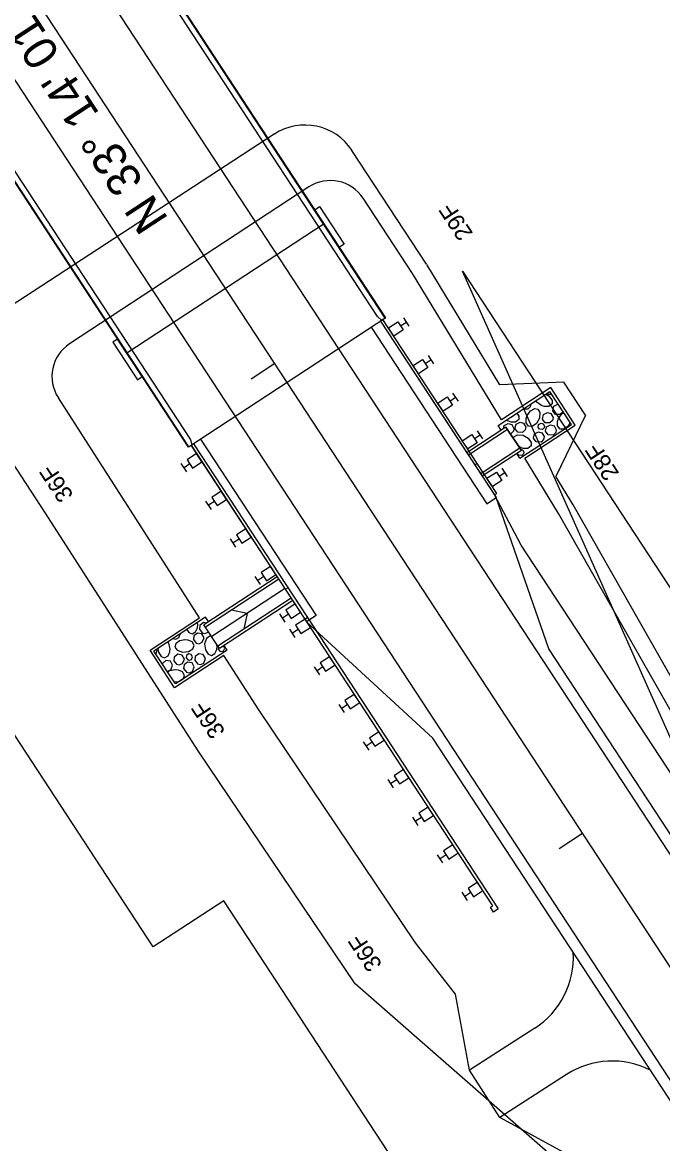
# Model space of a CAD drawing. Extents: x 1551641 to 1624343, y 1119533 to 1136600.
# Drawn here: x 1552624.3 to 1552738.3, y 1134110 to 1134309.5 of the extents above; entities that cross this region are included whole.
import ezdxf

# ---------------------------------------------------------------- set-up
doc = ezdxf.new("R2010")
doc.units = 0
for name, color, linetype in [('BR_CONCRETE', 7, 'Continuous'), ('Drainage-Trench', 7, 'Continuous'), ('RD_HC_CL_Rel', 7, 'Continuous'), ('RD_HC_Data', 7, 'Continuous'), ('RD_HC_Data_Tic', 7, 'Continuous'), ('RD_PD_BOC', 7, 'Continuous'), ('RD_PD_CstnLmt', 7, 'Continuous'), ('RD_PD_CstnLmt_TX', 7, 'Continuous'), ('RD_PD_DR_ErosCtrl', 7, 'Continuous'), ('RD_PD_DR_Inlet', 7, 'Continuous'), ('RD_PD_Driveway', 7, 'Continuous'), ('RD_PD_Final_TrvlWay', 7, 'Continuous'), ('RD_PD_GR', 7, 'Continuous'), ('RD_PD_PatLn1', 7, 'Continuous'), ('RD_PD_PaveDit', 7, 'Continuous'), ('RD_PD_PaveShd', 7, 'Continuous'), ('RD_PD_RW', 7, 'Continuous'), ('RD_Sketch8', 7, 'Continuous')]:
    doc.layers.add(name, color=color, linetype=linetype)

# ---------------------------------------------------------------- blocks, each defined once
blk = doc.blocks.new('Guardrail_MTBBC3_Transition')
at = {"layer": 'RD_PD_GR'}
for p, q in [((3.525, 3.75), (1.775, 3.75)), ((1.775, 0.5), (1.775, 2.5)), ((1.775, 2.5), (3.525, 2.5)), ((2.65, 2.5), (2.65, 3.75)), ((3.525, 2.5), (3.525, 0.5)), ((11.525, 3.75), (9.775, 3.75)), ((9.775, 0.5), (9.775, 2.5)), ((9.775, 2.5), (11.525, 2.5)), ((10.65, 2.5), (10.65, 3.75)), ((11.525, 2.5), (11.525, 0.5)), ((19.525, 3.75), (17.775, 3.75)), ((17.775, 0.5), (17.775, 2.5)), ((17.775, 2.5), (19.525, 2.5)), ((18.65, 2.5), (18.65, 3.75)), ((19.525, 2.5), (19.525, 0.5)), ((27.525, 3.75), (25.775, 3.75)), ((25.775, 0.5), (25.775, 2.5)), ((25.775, 2.5), (27.525, 2.5)), ((26.65, 2.5), (26.65, 3.75)), ((27.525, 2.5), (27.525, 0.5)), ((35.525, 3.75), (33.775, 3.75)), ((33.775, 0.5), (33.775, 2.5)), ((33.775, 2.5), (35.525, 2.5)), ((34.65, 2.5), (34.65, 3.75)), ((35.525, 2.5), (35.525, 0.5)), ((37, 0.5), (0, 0.5)), ((0, 0.5), (0, 0)), ((0, 0), (37, 0)), ((3.525, 0.5), (1.775, 0.5)), ((11.525, 0.5), (9.775, 0.5)), ((19.525, 0.5), (17.775, 0.5)), ((27.525, 0.5), (25.775, 0.5)), ((30.65, 0.5), (30.65, 0)), ((35.525, 0.5), (33.775, 0.5)), ((37, 0), (37, 0.5))]:
    blk.add_line(p, q, dxfattribs=at)

msp = doc.modelspace()

# ---------------------------------------------------------------- linework, layer by layer
at = {"layer": 'BR_CONCRETE'}
for p, q in [((1552688.91, 1134256.91), (1552612.18, 1134374.01)), ((1552688.98, 1134256.95), (1552612.25, 1134374.05)), ((1552653.85, 1134233.93), (1552577.12, 1134351.04)), ((1552653.92, 1134233.98), (1552577.19, 1134351.08)), ((1552678.02, 1134273.68), (1552642.89, 1134250.66)), ((1552688.98, 1134256.95), (1552653.85, 1134233.93))]:
    msp.add_line(p, q, dxfattribs=at)
for points in [[(1552688.28, 1134256.49), (1552687.53, 1134257.19), (1552611.9, 1134372.62), (1552611.56, 1134373.6)], [(1552654.55, 1134234.39), (1552654.21, 1134235.36), (1552578.58, 1134350.79), (1552577.82, 1134351.49)]]:
    msp.add_lwpolyline(points, dxfattribs=at)
for points in [[(1552680.76, 1134269.5), (1552676.38, 1134276.19), (1552677.21, 1134276.74), (1552681.6, 1134270.05)], [(1552645.63, 1134246.48), (1552641.25, 1134253.17), (1552640.41, 1134252.62), (1552644.79, 1134245.93)]]:
    msp.add_lwpolyline(points, close=True, dxfattribs=at)
at = {"layer": 'Drainage-Trench'}
for p, q in [((1552709.01, 1134237.8), (1552718.21, 1134243.82)), ((1552722.05, 1134237.97), (1552718.21, 1134243.82)), ((1552709.56, 1134236.96), (1552709.01, 1134237.8)), ((1552713.14, 1134233.32), (1552710.39, 1134237.51)), ((1552712.85, 1134231.94), (1552722.05, 1134237.97)), ((1552712.85, 1134231.94), (1552712.3, 1134232.78)), ((1552669.68, 1134210.83), (1552656.63, 1134202.28)), ((1552669.96, 1134210.41), (1552656.9, 1134201.86)), ((1552672.15, 1134207.07), (1552659.1, 1134198.52)), ((1552672.43, 1134206.65), (1552659.37, 1134198.1)), ((1552656.92, 1134203.66), (1552647.72, 1134197.63)), ((1552657.47, 1134202.83), (1552656.92, 1134203.66)), ((1552659.37, 1134198.1), (1552656.63, 1134202.28)), ((1552660.76, 1134197.81), (1552660.21, 1134198.64)), ((1552651.55, 1134191.78), (1552647.72, 1134197.63)), ((1552660.76, 1134197.81), (1552651.55, 1134191.78))]:
    msp.add_line(p, q, dxfattribs=at)
at = {"layer": 'RD_HC_CL_Rel'}
msp.add_line((1552832.44, 1133999.68), (1552472.39, 1134549.2), dxfattribs=at)
at = {"layer": 'RD_HC_Data_Tic'}
for p, q in [((1552669.22, 1134248.79), (1552665.04, 1134246.05)), ((1552724.03, 1134165.14), (1552719.85, 1134162.4))]:
    msp.add_line(p, q, dxfattribs=at)
at = {"layer": 'RD_PD_BOC'}
for p, q in [((1552688.08, 1134256.36), (1552708.65, 1134224.96)), ((1552686.4, 1134255.26), (1552706.98, 1134223.86)), ((1552656.01, 1134235.35), (1552676.59, 1134203.95)), ((1552654.34, 1134234.25), (1552674.91, 1134202.85)), ((1552706.98, 1134223.86), (1552708.65, 1134224.96)), ((1552676.59, 1134203.95), (1552674.91, 1134202.85))]:
    msp.add_line(p, q, dxfattribs=at)
at = {"layer": 'RD_PD_CstnLmt'}
for p, q in [((1552675.32, 1134280.25), (1552632.71, 1134252.33)), ((1552693.74, 1134264.85), (1552684.97, 1134278.23)), ((1552709.61, 1134238.79), (1552693.74, 1134264.85)), ((1552718.36, 1134244.52), (1552709.61, 1134238.79)), ((1552722.74, 1134237.82), (1552718.36, 1134244.52)), ((1552655.83, 1134203.55), (1552630.7, 1134242.68)), ((1552713.78, 1134231.95), (1552722.74, 1134237.82)), ((1552719.76, 1134222.13), (1552713.78, 1134231.95)), ((1552744.5, 1134178.56), (1552719.76, 1134222.13)), ((1552647.03, 1134197.78), (1552655.83, 1134203.55)), ((1552651.41, 1134191.09), (1552647.03, 1134197.78)), ((1552660.16, 1134196.82), (1552651.41, 1134191.09)), ((1552666.37, 1134187.14), (1552660.16, 1134196.82)), ((1552694.31, 1134145.67), (1552666.37, 1134187.14)), ((1552701.38, 1134136.53), (1552694.31, 1134145.67)), ((1552703.91, 1134123.01), (1552701.38, 1134136.53)), ((1552709.32, 1134114.6), (1552703.91, 1134123.01)), ((1552725, 1134106), (1552709.32, 1134114.6))]:
    msp.add_line(p, q, dxfattribs=at)
for centre, start, end in [((1552679.14, 1134274.41), 33.2337, 123.2337), ((1552636.53, 1134246.5), 123.2337, 213.2337)]:
    msp.add_arc(centre, 6.97, start, end, dxfattribs=at)
at = {"layer": 'RD_PD_DR_ErosCtrl'}
for p, q in [((1552669.15, 1134289.64), (1552620.56, 1134257.94)), ((1552696.25, 1134266.5), (1552682.98, 1134286.75)), ((1552709.33, 1134245.03), (1552696.3, 1134266.41)), ((1552720.72, 1134245.47), (1552709.33, 1134245.03)), ((1552724.56, 1134239.61), (1552720.72, 1134245.47)), ((1552628.41, 1134222.19), (1552616.79, 1134239.93)), ((1552724.56, 1134239.61), (1552719.29, 1134228.68)), ((1552722.35, 1134223.65), (1552719.29, 1134228.68)), ((1552747.11, 1134180.04), (1552722.35, 1134223.65)), ((1552655.59, 1134179.88), (1552628.41, 1134222.19)), ((1552683.53, 1134138.41), (1552655.59, 1134179.88)), ((1552722.56, 1134104.25), (1552683.53, 1134138.41))]:
    msp.add_line(p, q, dxfattribs=at)
msp.add_arc((1552674.62, 1134281.27), 10, 33.2337, 123.1181, dxfattribs=at)
at = {"layer": 'RD_PD_DR_Inlet'}
for p, q in [((1552710.39, 1134237.51), (1552703.42, 1134232.94)), ((1552710.67, 1134237.09), (1552703.7, 1134232.52)), ((1552710.39, 1134237.51), (1552713.14, 1134233.32)), ((1552712.86, 1134233.74), (1552705.89, 1134229.17)), ((1552713.14, 1134233.32), (1552706.16, 1134228.76))]:
    msp.add_line(p, q, dxfattribs=at)
at = {"layer": 'RD_PD_Driveway'}
for p, q in [((1552715.52, 1134130.49), (1552703.91, 1134123.01)), ((1552709.32, 1134114.6), (1552703.91, 1134123.01)), ((1552721.19, 1134122.25), (1552709.32, 1134114.6))]:
    msp.add_line(p, q, dxfattribs=at)
for centre, start, end in [((1552707.39, 1134143.1), 302.8006, 3.3073), ((1552729.31, 1134109.64), 63.1602, 122.8006)]:
    msp.add_arc(centre, 15, start, end, dxfattribs=at)
at = {"layer": 'RD_PD_Final_TrvlWay'}
for p, q in [((1552841.65, 1134005.71), (1552481.59, 1134555.23)), ((1552823.24, 1133993.65), (1552463.19, 1134543.17))]:
    msp.add_line(p, q, dxfattribs=at)
at = {"layer": 'RD_PD_GR'}
for p, q in [((1552713.11, 1134216.47), (1552708.35, 1134225.41)), ((1552748.3, 1134162.77), (1552713.11, 1134216.47)), ((1552674.62, 1134203.3), (1552672.94, 1134202.21)), ((1552674.62, 1134203.3), (1552675.04, 1134203.58)), ((1552675.58, 1134201.84), (1552674.62, 1134203.3)), ((1552708.05, 1134152.28), (1552674.62, 1134203.3)), ((1552675.04, 1134203.58), (1552709.01, 1134151.72)), ((1552672.86, 1134200.06), (1552671.9, 1134201.52)), ((1552673.42, 1134201.48), (1552672.38, 1134200.79)), ((1552672.94, 1134202.21), (1552673.9, 1134200.74)), ((1552673.9, 1134200.74), (1552675.58, 1134201.84)), ((1552679, 1134196.61), (1552677.33, 1134195.52)), ((1552679.96, 1134195.15), (1552679, 1134196.61)), ((1552677.24, 1134193.37), (1552676.28, 1134194.83)), ((1552677.81, 1134194.79), (1552676.76, 1134194.1)), ((1552677.33, 1134195.52), (1552678.29, 1134194.05)), ((1552678.29, 1134194.05), (1552679.96, 1134195.15)), ((1552683.39, 1134189.92), (1552681.71, 1134188.83)), ((1552681.71, 1134188.83), (1552682.67, 1134187.36)), ((1552682.67, 1134187.36), (1552684.35, 1134188.46)), ((1552684.35, 1134188.46), (1552683.39, 1134189.92)), ((1552681.63, 1134186.68), (1552680.67, 1134188.14)), ((1552682.19, 1134188.09), (1552681.15, 1134187.41)), ((1552687.77, 1134183.23), (1552686.1, 1134182.13)), ((1552688.73, 1134181.77), (1552687.77, 1134183.23)), ((1552686.01, 1134179.99), (1552685.05, 1134181.45)), ((1552686.58, 1134181.4), (1552685.53, 1134180.72)), ((1552686.1, 1134182.13), (1552687.06, 1134180.67)), ((1552687.06, 1134180.67), (1552688.73, 1134181.77)), ((1552692.16, 1134176.54), (1552690.48, 1134175.44)), ((1552693.11, 1134175.07), (1552692.16, 1134176.54)), ((1552690.4, 1134173.29), (1552689.44, 1134174.76)), ((1552690.96, 1134174.71), (1552689.92, 1134174.03)), ((1552690.48, 1134175.44), (1552691.44, 1134173.98)), ((1552691.44, 1134173.98), (1552693.11, 1134175.07)), ((1552696.54, 1134169.85), (1552694.87, 1134168.75)), ((1552694.87, 1134168.75), (1552695.83, 1134167.29)), ((1552697.5, 1134168.38), (1552696.54, 1134169.85)), ((1552694.78, 1134166.6), (1552693.82, 1134168.07)), ((1552695.35, 1134168.02), (1552694.3, 1134167.33)), ((1552695.83, 1134167.29), (1552697.5, 1134168.38)), ((1552700.92, 1134163.16), (1552699.25, 1134162.06)), ((1552701.88, 1134161.69), (1552700.92, 1134163.16)), ((1552699.16, 1134159.91), (1552698.21, 1134161.37)), ((1552699.73, 1134161.33), (1552698.69, 1134160.64)), ((1552699.25, 1134162.06), (1552700.21, 1134160.6)), ((1552700.21, 1134160.6), (1552701.88, 1134161.69)), ((1552705.31, 1134156.46), (1552703.64, 1134155.37)), ((1552706.27, 1134155), (1552705.31, 1134156.46)), ((1552703.55, 1134153.22), (1552702.59, 1134154.68)), ((1552704.12, 1134154.64), (1552703.07, 1134153.95)), ((1552703.64, 1134155.37), (1552704.59, 1134153.9)), ((1552704.59, 1134153.9), (1552706.27, 1134155)), ((1552707.63, 1134152.01), (1552708.05, 1134152.28)), ((1552708.18, 1134151.17), (1552707.63, 1134152.01)), ((1552709.01, 1134151.72), (1552708.18, 1134151.17))]:
    msp.add_line(p, q, dxfattribs=at)
at = {"layer": 'RD_PD_PatLn1'}
for p, q in [((1552670.99, 1134208.7), (1552658, 1134200.19)), ((1552664.29, 1134204.31), (1552661.52, 1134204.89)), ((1552664.29, 1134204.31), (1552663.72, 1134201.54))]:
    msp.add_line(p, q, dxfattribs=at)
at = {"layer": 'RD_PD_PaveDit'}
for p, q in [((1552718.52, 1134243.36), (1552718.45, 1134243.29)), ((1552714.26, 1134240.68), (1552713.46, 1134240.71)), ((1552710.79, 1134238.56), (1552710.5, 1134238.77)), ((1552711.25, 1134236.3), (1552711.18, 1134236.31)), ((1552712.97, 1134233.85), (1552712.64, 1134234.09)), ((1552655.51, 1134202.33), (1552655.43, 1134202.69)), ((1552652.17, 1134200.01), (1552652.47, 1134200.75)), ((1552657.39, 1134201.01), (1552657.42, 1134201.08)), ((1552658.95, 1134198.46), (1552658.87, 1134198.86)), ((1552648.02, 1134197.17), (1552648.11, 1134197.21))]:
    msp.add_line(p, q, dxfattribs=at)
for points in [[(1552717.49, 1134243.35), (1552718.1, 1134242.99), (1552718.62, 1134242.24), (1552718.59, 1134241.61), (1552718.01, 1134241.17), (1552717.24, 1134241.17), (1552716.66, 1134241.36)], [(1552718.45, 1134243.29), (1552717.92, 1134243.31), (1552717.76, 1134243.53)], [(1552714.16, 1134239.54), (1552714.74, 1134240.37), (1552715.51, 1134240.78), (1552716.07, 1134240.68), (1552716.44, 1134240.08), (1552716.36, 1134239.07), (1552715.81, 1134238.14), (1552715.06, 1134237.62), (1552714.43, 1134237.65), (1552713.99, 1134238.23), (1552713.99, 1134239), (1552714.18, 1134239.58)], [(1552714.8, 1134241.59), (1552714.71, 1134241.13), (1552714.26, 1134240.68)], [(1552716.7, 1134241.34), (1552715.88, 1134241.92), (1552715.73, 1134242.2)], [(1552720.07, 1134239.73), (1552719.2, 1134239.76), (1552718.72, 1134240.41), (1552718.9, 1134241.19), (1552719.62, 1134241.57), (1552719.7, 1134241.55)], [(1552712.35, 1134239.98), (1552712.71, 1134239.46), (1552712.68, 1134238.83), (1552712.1, 1134238.39), (1552711.33, 1134238.39), (1552710.75, 1134238.58)], [(1552713.36, 1134236.55), (1552712.48, 1134236.58), (1552712, 1134237.23), (1552712.18, 1134238.01), (1552712.91, 1134238.39), (1552713.52, 1134238.2), (1552713.91, 1134237.5), (1552713.81, 1134236.99), (1552713.36, 1134236.55)], [(1552718.22, 1134238.25), (1552717.35, 1134238.28), (1552716.87, 1134238.93), (1552717.05, 1134239.71), (1552717.77, 1134240.09), (1552718.39, 1134239.9), (1552718.78, 1134239.21), (1552718.68, 1134238.69), (1552718.22, 1134238.25)], [(1552721.82, 1134238.32), (1552721.41, 1134237.61), (1552720.66, 1134237.1), (1552720.03, 1134237.12), (1552719.59, 1134237.7), (1552719.58, 1134238.47), (1552719.77, 1134239.05)], [(1552719.75, 1134239.01), (1552720.34, 1134239.84), (1552720.7, 1134240.03)], [(1552720.55, 1134240.26), (1552720.53, 1134240.17), (1552720.07, 1134239.73)], [(1552709.95, 1134237.21), (1552710.07, 1134237.77), (1552710.8, 1134238.14), (1552711.42, 1134237.95), (1552711.8, 1134237.26), (1552711.71, 1134236.75), (1552711.25, 1134236.3)], [(1552716.64, 1134234.83), (1552715.76, 1134234.86), (1552715.28, 1134235.51), (1552715.46, 1134236.29), (1552716.18, 1134236.67), (1552716.8, 1134236.48), (1552717.19, 1134235.79), (1552717.09, 1134235.27), (1552716.64, 1134234.83)], [(1552716.92, 1134237.09), (1552716.39, 1134237.1), (1552716.1, 1134237.49), (1552716.21, 1134237.96), (1552716.64, 1134238.19), (1552717.01, 1134238.08), (1552717.25, 1134237.66), (1552717.19, 1134237.35), (1552716.91, 1134237.09)], [(1552718.8, 1134236.08), (1552717.92, 1134236.11), (1552717.44, 1134236.75), (1552717.62, 1134237.54), (1552718.34, 1134237.92), (1552718.96, 1134237.73), (1552719.35, 1134237.03), (1552719.25, 1134236.52), (1552718.8, 1134236.08)], [(1552711.76, 1134235.42), (1552711.82, 1134235.76), (1552712.42, 1134236.14), (1552713.43, 1134236.05), (1552714.36, 1134235.51), (1552714.88, 1134234.76), (1552714.85, 1134234.13), (1552714.27, 1134233.69), (1552713.5, 1134233.68), (1552712.92, 1134233.87)], [(1552713.22, 1134232.46), (1552712.69, 1134232.48), (1552712.41, 1134232.85)], [(1552712.99, 1134233.55), (1552713.32, 1134233.45), (1552713.55, 1134233.03), (1552713.49, 1134232.72), (1552713.22, 1134232.46)], [(1552653.58, 1134201.48), (1552653.92, 1134200.94), (1552654.5, 1134200.71), (1552655.13, 1134201.07), (1552655.45, 1134201.77), (1552655.51, 1134202.38)], [(1552657.08, 1134202.57), (1552656.52, 1134202.68), (1552655.89, 1134202.16), (1552655.81, 1134201.52), (1552656.3, 1134200.89), (1552656.8, 1134200.77), (1552657.39, 1134201.01)], [(1552656.33, 1134199.18), (1552656.65, 1134199.99), (1552656.25, 1134200.69), (1552655.45, 1134200.84), (1552654.82, 1134200.33), (1552654.74, 1134199.69), (1552655.23, 1134199.05), (1552655.74, 1134198.94), (1552656.32, 1134199.18)], [(1552650.6, 1134198.02), (1552650.39, 1134199.02), (1552650.2, 1134199.26)], [(1552651.13, 1134199.87), (1552651.59, 1134199.77), (1552652.17, 1134200.01)], [(1552653.27, 1134199.64), (1552652.27, 1134199.43), (1552651.59, 1134198.9), (1552651.46, 1134198.34), (1552651.86, 1134197.76), (1552652.82, 1134197.44), (1552653.89, 1134197.56), (1552654.66, 1134198.05), (1552654.89, 1134198.63), (1552654.53, 1134199.27), (1552653.83, 1134199.58), (1552653.22, 1134199.64)], [(1552658, 1134200.19), (1552657.66, 1134200.27), (1552657.08, 1134199.88), (1552656.75, 1134198.91), (1552656.88, 1134197.84), (1552657.36, 1134197.07), (1552657.95, 1134196.84), (1552658.58, 1134197.2), (1552658.9, 1134197.9), (1552658.95, 1134198.51)], [(1552660.13, 1134197.67), (1552660.32, 1134198.16), (1552660.09, 1134198.57)], [(1552648.11, 1134197.21), (1552648.31, 1134197.7), (1552648.17, 1134197.93)], [(1552648.44, 1134198.11), (1552648.52, 1134197.4), (1552649.01, 1134196.63), (1552649.59, 1134196.4), (1552650.23, 1134196.76), (1552650.54, 1134197.46), (1552650.6, 1134198.07)], [(1552652.82, 1134195.4), (1552653.15, 1134196.21), (1552652.74, 1134196.91), (1552651.95, 1134197.06), (1552651.32, 1134196.55), (1552651.24, 1134195.91), (1552651.73, 1134195.27), (1552652.23, 1134195.16), (1552652.82, 1134195.4)], [(1552654.41, 1134196.13), (1552654.61, 1134196.62), (1552654.37, 1134197.04), (1552653.89, 1134197.13), (1552653.51, 1134196.82), (1552653.46, 1134196.44), (1552653.76, 1134196.06), (1552654.06, 1134195.99), (1552654.41, 1134196.13)], [(1552656.59, 1134195.49), (1552656.92, 1134196.3), (1552656.51, 1134197), (1552655.72, 1134197.15), (1552655.08, 1134196.64), (1552655.01, 1134196), (1552655.5, 1134195.36), (1552656, 1134195.25), (1552656.59, 1134195.49)], [(1552659.22, 1134198.32), (1552659.18, 1134197.98), (1552659.47, 1134197.6), (1552659.78, 1134197.53), (1552660.13, 1134197.67)], [(1552650.73, 1134194.29), (1552651.05, 1134195.11), (1552650.65, 1134195.81), (1552649.85, 1134195.96), (1552649.22, 1134195.44), (1552649.21, 1134195.36)], [(1552654.59, 1134194.01), (1552654.91, 1134194.82), (1552654.51, 1134195.52), (1552653.71, 1134195.67), (1552653.08, 1134195.16), (1552653.01, 1134194.51), (1552653.49, 1134193.88), (1552654, 1134193.77), (1552654.59, 1134194.01)], [(1552650.05, 1134194.07), (1552650.14, 1134194.05), (1552650.73, 1134194.29)], [(1552651.52, 1134194.3), (1552650.52, 1134194.09), (1552650.2, 1134193.84)], [(1552651.33, 1134192.13), (1552652.14, 1134192.22), (1552652.91, 1134192.71), (1552653.14, 1134193.29), (1552652.78, 1134193.93), (1552652.08, 1134194.24), (1552651.47, 1134194.3)]]:
    msp.add_lwpolyline(points, dxfattribs=at)
at = {"layer": 'RD_PD_PaveShd'}
for p, q in [((1552718.03, 1134198.02), (1552708.65, 1134224.96)), ((1552697.38, 1134182.1), (1552674.91, 1134202.85)), ((1552843.32, 1134006.81), (1552718.03, 1134198.02)), ((1552821.57, 1133992.56), (1552697.38, 1134182.1))]:
    msp.add_line(p, q, dxfattribs=at)
at = {"layer": 'RD_PD_RW'}
for p, q in [((1552647.6, 1134144.95), (1552409.65, 1134508.1)), ((1552660.14, 1134153.17), (1552647.6, 1134144.95)), ((1552782.26, 1133966.8), (1552660.14, 1134153.17))]:
    msp.add_line(p, q, dxfattribs=at)
at = {"layer": 'RD_Sketch8'}
for p, q in [((1552702.65, 1134265.28), (1552790.34, 1134131.45)), ((1552768.59, 1134117.2), (1552702.65, 1134265.28))]:
    msp.add_line(p, q, dxfattribs=at)

# ---------------------------------------------------------------- block references
at = {"layer": 'RD_PD_CstnLmt', "rotation": -56.76625394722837}
msp.add_blockref('Guardrail_MTBBC3_Transition', (1552688.08, 1134256.36), dxfattribs=at)
at = {"layer": 'RD_PD_CstnLmt', "yscale": -0.9999999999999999, "rotation": -56.766253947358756}
msp.add_blockref('Guardrail_MTBBC3_Transition', (1552654.76, 1134234.53), dxfattribs=at)

# ---------------------------------------------------------------- texts
at = {"layer": 'RD_HC_Data'}
msp.add_text('N 33%%d 14\' 01.5" W', height=6, rotation=123.2337, dxfattribs=at).set_placement((1552650.4, 1134274.52))
at = {"layer": 'RD_PD_CstnLmt_TX'}
for s, p in [('29F', (1552704.61, 1134271.98)), ('28F', (1552730.64, 1134229.25)), ('36F', (1552633.49, 1134225.38)), ('36F', (1552660.52, 1134183.31)), ('36F', (1552688.45, 1134141.83))]:
    msp.add_text(s, height=3, rotation=123.2337, dxfattribs=at).set_placement(p)

doc.saveas('drawing.dxf')
